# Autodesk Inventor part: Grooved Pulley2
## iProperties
Created: 2011-05
Part Number: Grooved Pulley2
Material: Steel
Document SubType Name: Modeling
Designer: 904Chiaki
Density: 1 g/cm^3
CustomPartVersion: 1
Author: 904Chiaki
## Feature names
1. Body [Revolution]
2. Groove [Revolution]
3. Fillet External
4. Fillet Internal
5. Groove Pattern [Rectangular Pattern]
6. Extrusion1
7. Extrusion2
8. Mirror1
9. Extrusion3
10. Fillet3
11. Fillet4
12. Extrusion4
13. Fillet5
14. Fillet6
